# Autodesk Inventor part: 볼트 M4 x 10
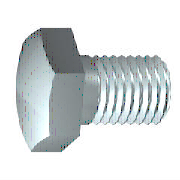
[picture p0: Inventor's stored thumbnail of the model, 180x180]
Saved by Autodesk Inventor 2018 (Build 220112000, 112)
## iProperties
Created: 2012-02
Part Number: 볼트 M4 x 10
Material: 스테인리스강
Description: 6각 머리 나사
Document SubType Name: Modeling
Standard: ISO 4017
Designer: mduedu
Standard Revision: Third edition 1999-08-15
Standards Organization: ISO
Language: ko-KR
Size Designation: M4 x 10
Categories: <MemberInstance><Categories><Category DisplayName="조임쇠" InternalName="e4da775c-781d-43d5-af7c-5136215cf5a6" Mnemonic="FSTN"><Category DisplayName="볼트" InternalN
Density: 8.08 g/cm^3
Appearance: 기본값
IsCustomPart: 0
Author: mduedu
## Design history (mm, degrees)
sketch "스케치1"
  geometry: L1 (0, 3.015)-(0, 2); L2 (2.1, 2)-(10, 2); L3 (10, 2)-(10, 0); L4 (10, 0)-(-0.4, 0); L5 (-2.48, 0)-(12.08, 0) reference; L6 (-0.4, 0)-(-0.4, 3.015); L7 (-0.4, 3.015)-(0, 3.015); L8 (2.1, 2)-(1.67, 2); L9 (1.67, 2)-(0, 2); L10 (0, -0.603)-(0, 3.618) reference
  constraints: 16 end point, 2 collinear, 2 perpendicular, 1 parallel
  dimensions: "d0" = 10 distance between parallel lines of L3 L1 (= NLG); "d1" = 7.9 distance from line of L2.start L3 (= GEL); "d2" = 4 diameter of L2 L4 (= GD); "d9" = 0.4001 distance between parallel lines of L6 L1 (computed from SD); "d10" = 6.03 diameter of L7 L4 (= SD2); "d13" = 0.42952 distance of L2.start L8.end (computed from GAL); "d14" = 4 diameter of L9 L4 (= BDM)
revolve "본체" sketch "스케치1" stored, may be unused: angle "d12" = 90 deg
sketch "스케치2"
  geometry: L1 (0, 4.041)-(3.5, 2.021); L2 (3.5, 2.021)-(3.5, -2.021); L3 (3.5, -2.021)-(0, -4.041); L4 (0, -4.041)-(-3.5, -2.021); L5 (-3.5, -2.021)-(-3.5, 2.021); L6 (-3.5, 2.021)-(0, 4.041); 2 further points
  constraints: 12 end point, 1 coincident, 1 vertical, 11 other
  dimensions: "d11" = 7 distance between parallel lines of L5 L2 (= SW)
extrude "머리" join sketch "스케치2" distance "d3" = 2.4 (= KOH - SD); taper "d4" = 0 deg
sketch "스케치4"
  geometry: L1 (-2.8, 3.5)-(-2.8, 4.041); L2 (-2.8, 4.041)-(-2.487, 4.041); L3 (-2.487, 4.041)-(-2.8, 3.5); L4 (-3.28, 0)-(0.08, 0) reference; L5 (-0.4, 4.041)-(-2.8, 4.041) reference; L6 (-2.8, 2.021)-(-2.8, 4.041) reference
  constraints: 6 end point, 2 collinear, 1 perpendicular, 1 vertical
  dimensions: "d5" = 30 deg angle of L3 L1 (= ANG1); "d19" = 7 diameter of L1.start L4 (= SW0)
revolve "모따기1" sketch "스케치4" stored, may be unused: angle "d21" = 90 deg
workplane "Work Plane1"
body "Solid1"
feature "스레드" dims "d15" = 7.9 (= GEL), "d16" = 0
chamfer "모따기2" distance "d6" = 0.42941 (= -0.5 x SPD + 0.5 x GD); stored, may be unused: second distance "d7" = 0.42952 (computed from GUL), angle "d55" = 45 deg
other parameters: "NLG" = 10 [user parameter; used in 1 equation term], "GD" = 4 (= NND) [user parameter; used in 2 equation terms], "BDM" = 4 (= NND) [user parameter; used in 1 equation term], "KOH" = 2.8 [user parameter; used in 1 equation term], "GEL" = 7.9 [user parameter; used in 2 equation terms], "SW" = 7 [user parameter; used in 2 equation terms], "SW0" = 7 (= SW) [user parameter; used in 1 equation term], "SPD" = 3.14117 (= NND - 1.2269 x PTC) [user parameter; used in 1 equation term], "SD2" = 6.03 [user parameter; used in 2 equation terms], "SD" = 0.4 [user parameter; used in 2 equation terms], "ANG1" = 30 deg [user parameter; used in 1 equation term], "GAL" = 0.42941 (= 0.61345 x PTC) [user parameter; used in 1 equation term], "GUL" = 0.42941 (= 0.61345 x PTC) [user parameter; used in 1 equation term], "d8" = 0, "RR" = 0.2 [user parameter], "d57" = 0, "d58" = 0, "TPU" = 14.28571 (computed from PTC) [user parameter], "GD1" = 3.14117 (= THREADDIA - 1.2269 x PTC) [user parameter], "THREADDIA" = 4 [user parameter; used in 1 equation term], "SDH" = 6.03 (= SD2) [user parameter], "SDHG" = 2.1 [user parameter], "TOA" = 30 deg [user parameter], "PTC" = 0.7 [user parameter; used in 5 equation terms], "NND" = 4 [user parameter; used in 3 equation terms], "E0" = 8.085 [user parameter]
